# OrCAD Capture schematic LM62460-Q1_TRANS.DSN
size D; title: LM62460-Q1: 6A Automotive Buck Converter; rev: 1.0; note: Datasheet: SNVSBQ1     EVM: SNVU682; note: Synchronous Step Down Converter
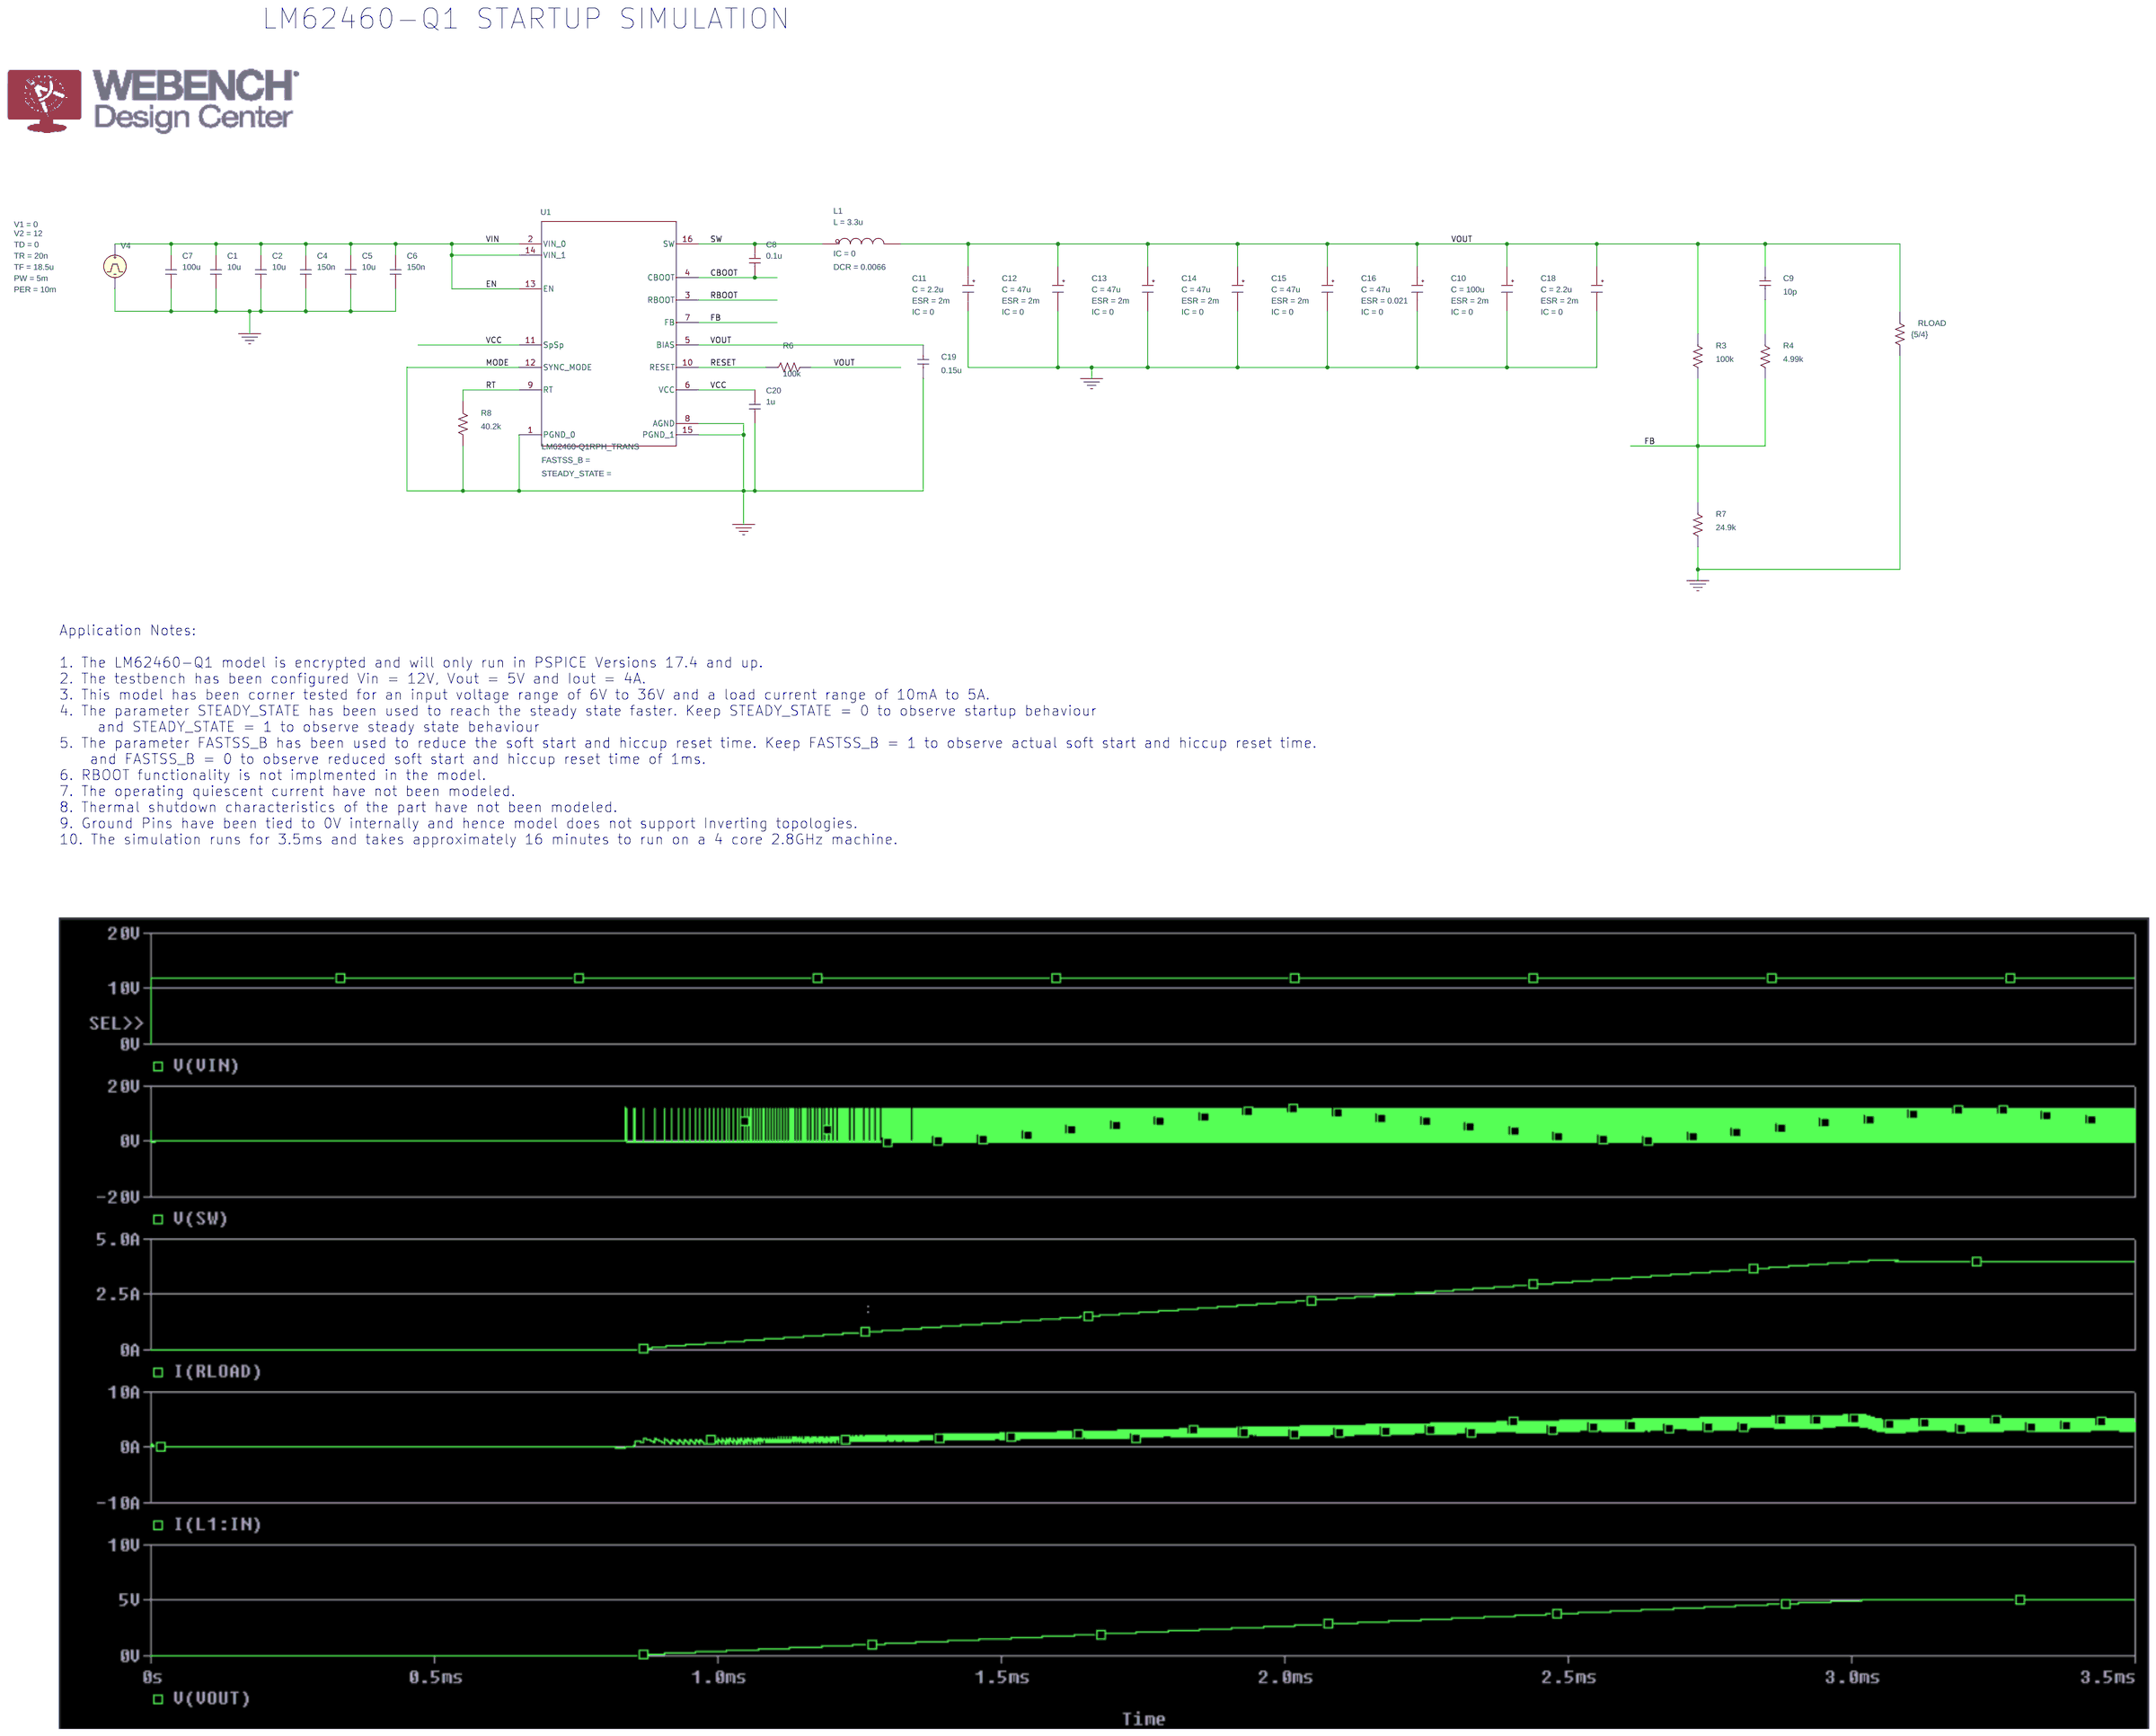
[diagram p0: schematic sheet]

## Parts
C1  10u  [RAD/CK05]
C2  10u  [RAD/CK05]
C4  150n  [RAD/CK05]
C5  10u  [RAD/CK05]
C6  150n  [RAD/CK05]
C7  100u  [RAD/CK05]
C8  0.1u  [RAD/CK05]
C9  10p  [RAD/CK05]
C10  CESR
C11  CESR
C12  CESR
C13  CESR
C14  CESR
C15  CESR
C16  CESR
C18  CESR
C19  0.15u  [RAD/CK05]
C20  1u  [RAD/CK05]
L1  LDCR
R3  100k  [AX/RC05]
R4  4.99k  [AX/RC05]
R6  100k  [AX/RC05]
R7  24.9k  [AX/RC05]
R8  40.2k  [AX/RC05]
RLOAD  {5/4}  [AX/RC05]
U1  LM62460-Q1RPH_TRANS  [RPH0016A]
V4  VPULSE

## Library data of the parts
C1 C2 C4-C9 C19 C20 = C
C10 = CESR_0: C: 100u; ESR: 2m; IC: 0; PSpiceTemplate: X^@REFDES %IN %OUT @MODEL PARAMS:  ?C|C=@C||C=100u|  ?ESR|ESR=@ESR||ESR=0.01| ?X|X=@X||X=2|  ?IC|IC=@IC||IC=2|; X: 1
C11 C18 = CESR_0: C: 2.2u; ESR: 2m; IC: 0; PSpiceTemplate: X^@REFDES %IN %OUT @MODEL PARAMS:  ?C|C=@C||C=100u|  ?ESR|ESR=@ESR||ESR=0.01| ?X|X=@X||X=2|  ?IC|IC=@IC||IC=2|; X: 1
C12-C15 = CESR_0: C: 47u; ESR: 2m; IC: 0; PSpiceTemplate: X^@REFDES %IN %OUT @MODEL PARAMS:  ?C|C=@C||C=100u|  ?ESR|ESR=@ESR||ESR=0.01| ?X|X=@X||X=2|  ?IC|IC=@IC||IC=2|; X: 1
C16 = CESR_0: C: 47u; ESR: 0.021; IC: 0; PSpiceTemplate: X^@REFDES %IN %OUT @MODEL PARAMS:  ?C|C=@C||C=100u|  ?ESR|ESR=@ESR||ESR=0.01| ?X|X=@X||X=2|  ?IC|IC=@IC||IC=2|; X: 1
L1 = LDCR_0: DCR: 0.0066; IC: 0; L: 3.3u; PSpiceTemplate: X^@REFDES %IN %OUT @MODEL PARAMS:  ?L|L=@L||L=1u|  ?DCR|DCR=@DCR||DCR=0.01| ?IC|IC=@IC||IC=0|
R3 R4 R7 RLOAD = r
R6 = r_1
R8 = r_2
U1 = LM62460-Q1RPH_TRANS
V4 = VPULSE: PER: 10m; PW: 5m; TD: 0; TF: 18.5u; TR: 20n; V1: 0; V2: 12

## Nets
VCC: C20.1 U1.6(VCC) U1.11(SpSp)
0: C1.2 C2.2 C4.2 C5.2 C6.2 C7.2 C10.2(OUT) C11.2(OUT) C12.2(OUT) C13.2(OUT) C14.2(OUT) C15.2(OUT) C16.2(OUT) C18.2(OUT) C19.2 C20.2 R7.2 R8.2 RLOAD.2 U1.1(PGND_0) U1.8(AGND) U1.12(SYNC_MODE) U1.15(PGND_1) V4.2(-)
CBOOT: C8.2 U1.4(CBOOT)
EN: C1.1 C2.1 C4.1 C5.1 C6.1 C7.1 U1.2(VIN_0) U1.13(EN) U1.14(VIN_1) V4.1(+)
FB: R3.2 R4.2 R7.1 U1.7(FB)
RBOOT: U1.3(RBOOT)
RESET: R6.1 U1.10(RESET)
RT: R8.1 U1.9(RT)
SW: C8.1 L1.1(IN) U1.16(SW)
VOUT: C9.1 C10.1(IN) C11.1(IN) C12.1(IN) C13.1(IN) C14.1(IN) C15.1(IN) C16.1(IN) C18.1(IN) C19.1 L1.3(OUT) R3.1 R6.2 RLOAD.1 U1.5(BIAS)
N16770953: C9.2 R4.1

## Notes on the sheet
- LM62460-Q1 STARTUP SIMULATION
- Application Notes:
  1. The LM62460-Q1 model is encrypted and will only run in PSPICE Versions 17.4 and up.
  2. The testbench has been configured Vin = 12V, Vout = 5V and Iout = 4A.
  3. This model has been corner tested for an input voltage range of 6V to 36V and a load current range of 10mA to 5A.
  4. The parameter STEADY_STATE has been used to reach the steady state faster. Keep STEADY_STATE = 0 to observe startup behaviour
       and STEADY_STATE = 1 to observe steady state behaviour
  5. The parameter FASTSS_B has been used to reduce the soft start and hiccup reset time. Keep FASTSS_B = 1 to observe actual soft start and hiccup reset time.
      and FASTSS_B = 0 to observe reduced soft start and hiccup reset time of 1ms.
  6. RBOOT functionality is not implmented in the model.
  7. The operating quiescent current have not been modeled.
  8. Thermal shutdown characteristics of the part have not been modeled.
  9. Ground Pins have been tied to 0V internally and hence model does not support Inverting topologies.
  10. The simulation runs for 3.5ms and takes approximately 16 minutes to run on a 4 core 2.8GHz machine.
